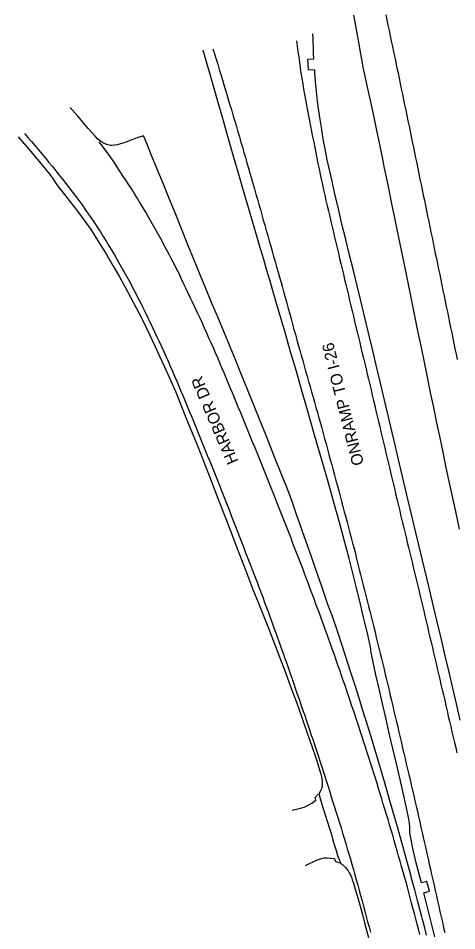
# Model space of a CAD drawing. Extents: x 1948091 to 1975253, y 787267 to 823306.
# Drawn here: x 1966396.6 to 1966599.2, y 789115.5 to 789536.5 of the extents above; entities that cross this region are included whole.
import ezdxf

# ---------------------------------------------------------------- set-up
doc = ezdxf.new("R2010")
doc.units = 0
for name, color, linetype in [('RD_EX_Pavement_Markings', 7, 'Continuous'), ('RD_EX_Road', 7, 'Continuous'), ('RD_TX_RoadID', 7, 'Continuous')]:
    doc.layers.add(name, color=color, linetype=linetype)

msp = doc.modelspace()

# ---------------------------------------------------------------- linework, layer by layer
at = {"layer": 'RD_EX_Pavement_Markings'}
for points in [[(1966566.37, 789538.15), (1966566.89, 789535.71), (1966567.41, 789533.26), (1966567.92, 789530.82), (1966568.44, 789528.37), (1966568.96, 789525.92), (1966569.47, 789523.48), (1966569.99, 789521.03), (1966570.51, 789518.59), (1966571.02, 789516.14), (1966571.54, 789513.7), (1966572.05, 789511.25), (1966572.57, 789508.81), (1966573.08, 789506.36), (1966573.58, 789503.91), (1966574.09, 789501.46), (1966574.6, 789499.01), (1966575.1, 789496.57), (1966575.61, 789494.12), (1966576.12, 789491.67), (1966576.62, 789489.22), (1966577.13, 789486.77), (1966577.63, 789484.33), (1966578.14, 789481.88), (1966578.65, 789479.43), (1966579.15, 789476.98), (1966579.66, 789474.54), (1966580.17, 789472.09), (1966580.67, 789469.64), (1966581.18, 789467.19), (1966581.68, 789464.74), (1966582.19, 789462.3), (1966582.7, 789459.85), (1966583.2, 789457.4), (1966583.71, 789454.95), (1966584.22, 789452.5), (1966584.72, 789450.06), (1966585.23, 789447.61), (1966585.74, 789445.16), (1966586.24, 789442.71), (1966586.75, 789440.27), (1966587.25, 789437.82), (1966587.76, 789435.37), (1966588.27, 789432.92), (1966588.77, 789430.47), (1966589.28, 789428.03), (1966589.78, 789425.58), (1966590.29, 789423.13), (1966590.79, 789420.68), (1966591.3, 789418.23), (1966591.8, 789415.78), (1966592.31, 789413.34), (1966592.81, 789410.89), (1966593.32, 789408.44), (1966593.82, 789405.99), (1966594.33, 789403.54), (1966594.83, 789401.1), (1966595.34, 789398.65), (1966595.84, 789396.2), (1966596.35, 789393.75), (1966596.85, 789391.3), (1966597.36, 789388.85), (1966597.86, 789386.41), (1966598.37, 789383.96), (1966598.88, 789381.51), (1966599.38, 789379.06)], [(1966525.18, 789526.08), (1966525.51, 789523.61), (1966525.85, 789521.13), (1966526.18, 789518.65), (1966526.51, 789516.18), (1966526.85, 789513.7), (1966527.22, 789511.23), (1966527.62, 789508.76), (1966528.02, 789506.3), (1966528.42, 789503.83), (1966528.82, 789501.37), (1966529.25, 789498.9), (1966529.73, 789496.45), (1966530.21, 789494), (1966530.69, 789491.55), (1966531.16, 789489.1), (1966531.64, 789486.65), (1966532.12, 789484.2), (1966532.61, 789481.75), (1966533.1, 789479.3), (1966533.58, 789476.85), (1966534.07, 789474.4), (1966534.56, 789471.95), (1966535.05, 789469.51), (1966535.58, 789467.07), (1966536.11, 789464.63), (1966536.63, 789462.19), (1966537.16, 789459.75), (1966537.68, 789457.31), (1966538.22, 789454.87), (1966538.79, 789452.44), (1966539.36, 789450.01), (1966539.93, 789447.58), (1966540.5, 789445.15), (1966541.07, 789442.72), (1966541.64, 789440.3), (1966542.21, 789437.87), (1966542.79, 789435.44), (1966543.36, 789433.01), (1966543.94, 789430.58), (1966544.51, 789428.16), (1966545.09, 789425.73), (1966545.66, 789423.3), (1966546.24, 789420.88), (1966546.81, 789418.45), (1966547.39, 789416.02), (1966547.96, 789413.59), (1966548.54, 789411.17), (1966549.12, 789408.74), (1966549.7, 789406.31), (1966550.27, 789403.89), (1966550.85, 789401.46), (1966551.43, 789399.03), (1966552.01, 789396.61), (1966552.59, 789394.18), (1966553.17, 789391.75), (1966553.76, 789389.33), (1966554.35, 789386.9), (1966554.93, 789384.48), (1966555.52, 789382.05), (1966556.11, 789379.63), (1966556.69, 789377.2), (1966557.28, 789374.78), (1966557.87, 789372.35), (1966558.45, 789369.93), (1966559.02, 789367.5), (1966559.59, 789365.07), (1966560.16, 789362.64), (1966560.73, 789360.21), (1966561.31, 789357.78), (1966561.88, 789355.35), (1966562.45, 789352.93), (1966563.02, 789350.5), (1966563.59, 789348.07), (1966564.16, 789345.64), (1966564.75, 789343.21), (1966565.33, 789340.79), (1966565.91, 789338.36), (1966566.49, 789335.94), (1966567.07, 789333.51), (1966567.65, 789331.09), (1966568.23, 789328.66), (1966568.81, 789326.24), (1966569.39, 789323.81), (1966569.97, 789321.38), (1966570.55, 789318.96), (1966571.12, 789316.53), (1966571.7, 789314.1), (1966572.28, 789311.68), (1966572.85, 789309.25), (1966573.43, 789306.82), (1966574, 789304.39), (1966574.58, 789301.97), (1966575.16, 789299.54), (1966575.74, 789297.11), (1966576.33, 789294.69), (1966576.91, 789292.26), (1966577.5, 789289.84), (1966578.09, 789287.41), (1966578.67, 789284.99), (1966579.26, 789282.56), (1966579.85, 789280.14), (1966580.43, 789277.71), (1966581.02, 789275.29), (1966581.61, 789272.86), (1966582.18, 789270.43), (1966582.76, 789268.01), (1966583.33, 789265.58), (1966583.9, 789263.15), (1966584.48, 789260.72), (1966585.05, 789258.29), (1966585.62, 789255.86), (1966586.2, 789253.43), (1966586.77, 789251.01), (1966587.34, 789248.58), (1966587.92, 789246.15), (1966588.49, 789243.72), (1966589.07, 789241.29), (1966589.64, 789238.86), (1966590.2, 789236.43), (1966590.77, 789234), (1966591.34, 789231.57), (1966591.9, 789229.14), (1966592.47, 789226.71), (1966593.03, 789224.28), (1966593.6, 789221.85), (1966594.16, 789219.42), (1966594.72, 789216.99), (1966595.28, 789214.56), (1966595.85, 789212.13), (1966596.41, 789209.7), (1966596.98, 789207.27), (1966597.55, 789204.84), (1966598.13, 789202.41), (1966598.7, 789199.98), (1966599.27, 789197.55)], [(1966486.58, 789522.44), (1966487.31, 789520.05), (1966488.05, 789517.66), (1966488.78, 789515.28), (1966489.5, 789512.88), (1966490.23, 789510.49), (1966490.95, 789508.1), (1966491.67, 789505.71), (1966492.39, 789503.32), (1966493.11, 789500.92), (1966493.83, 789498.53), (1966494.55, 789496.14), (1966495.27, 789493.75), (1966495.99, 789491.36), (1966496.71, 789488.96), (1966497.42, 789486.57), (1966498.11, 789484.17), (1966498.81, 789481.77), (1966499.51, 789479.37), (1966500.2, 789476.98), (1966500.9, 789474.58), (1966501.59, 789472.18), (1966502.29, 789469.78), (1966502.98, 789467.39), (1966503.68, 789464.99), (1966504.37, 789462.59), (1966505.05, 789460.19), (1966505.73, 789457.79), (1966506.42, 789455.39), (1966507.1, 789452.99), (1966507.79, 789450.59), (1966508.47, 789448.19), (1966509.15, 789445.8), (1966509.84, 789443.4), (1966510.52, 789441), (1966511.21, 789438.6), (1966511.89, 789436.2), (1966512.57, 789433.8), (1966513.25, 789431.4), (1966513.93, 789429), (1966514.61, 789426.6), (1966515.29, 789424.2), (1966515.97, 789421.8), (1966516.65, 789419.41), (1966517.33, 789417.01), (1966518.01, 789414.61), (1966518.69, 789412.21), (1966519.37, 789409.8), (1966520.03, 789407.4), (1966520.69, 789404.99), (1966521.36, 789402.59), (1966522.02, 789400.18), (1966522.68, 789397.78), (1966523.35, 789395.37), (1966524.01, 789392.97), (1966524.67, 789390.56), (1966525.34, 789388.16), (1966526, 789385.75), (1966526.66, 789383.35), (1966527.34, 789380.94), (1966528.02, 789378.55), (1966528.71, 789376.15), (1966529.39, 789373.74), (1966530.07, 789371.34), (1966530.76, 789368.94), (1966531.44, 789366.54), (1966532.12, 789364.14), (1966532.81, 789361.74), (1966533.49, 789359.34), (1966534.17, 789356.94), (1966534.85, 789354.54), (1966535.52, 789352.14), (1966536.18, 789349.73), (1966536.84, 789347.33), (1966537.49, 789344.92), (1966538.15, 789342.51), (1966538.81, 789340.1), (1966539.46, 789337.7), (1966540.12, 789335.29), (1966540.78, 789332.88), (1966541.43, 789330.47), (1966542.09, 789328.07), (1966542.75, 789325.66), (1966543.4, 789323.25), (1966544.05, 789320.84), (1966544.69, 789318.43), (1966545.33, 789316.02), (1966545.97, 789313.61), (1966546.61, 789311.2), (1966547.25, 789308.79), (1966547.9, 789306.38), (1966548.54, 789303.97), (1966549.18, 789301.56), (1966549.82, 789299.14), (1966550.46, 789296.73), (1966551.1, 789294.32), (1966551.73, 789291.91), (1966552.34, 789289.49), (1966552.95, 789287.07), (1966553.56, 789284.65), (1966554.17, 789282.23), (1966554.78, 789279.81), (1966555.39, 789277.39), (1966556, 789274.98), (1966556.61, 789272.56), (1966557.22, 789270.14), (1966557.83, 789267.72), (1966558.44, 789265.3), (1966559.05, 789262.88), (1966559.65, 789260.46), (1966560.24, 789258.03), (1966560.84, 789255.61), (1966561.43, 789253.19), (1966562.03, 789250.76), (1966562.62, 789248.34), (1966563.21, 789245.92), (1966563.81, 789243.49), (1966564.4, 789241.07), (1966565, 789238.64), (1966565.59, 789236.22), (1966566.19, 789233.8), (1966566.76, 789231.37), (1966567.33, 789228.94), (1966567.91, 789226.51), (1966568.48, 789224.08), (1966569.05, 789221.66), (1966569.62, 789219.23), (1966570.19, 789216.8), (1966570.77, 789214.37), (1966571.34, 789211.94), (1966571.91, 789209.51), (1966572.48, 789207.08), (1966573.06, 789204.65), (1966573.62, 789202.22), (1966574.19, 789199.79), (1966574.76, 789197.36), (1966575.33, 789194.93), (1966575.89, 789192.5), (1966576.46, 789190.07), (1966577.03, 789187.64), (1966577.59, 789185.21), (1966578.16, 789182.78), (1966578.73, 789180.35), (1966579.29, 789177.91), (1966579.86, 789175.48), (1966580.43, 789173.05), (1966580.98, 789170.62), (1966581.53, 789168.19), (1966582.08, 789165.75), (1966582.63, 789163.32), (1966583.18, 789160.88), (1966583.74, 789158.45), (1966584.29, 789156.01), (1966584.84, 789153.58), (1966585.39, 789151.14), (1966585.94, 789148.71), (1966586.49, 789146.28), (1966587.04, 789143.84), (1966587.59, 789141.41), (1966588.14, 789138.97), (1966588.69, 789136.54), (1966589.24, 789134.1), (1966589.79, 789131.67), (1966590.34, 789129.23), (1966590.89, 789126.8), (1966591.44, 789124.36), (1966591.99, 789121.92), (1966592.54, 789119.49), (1966593.09, 789117.05), (1966593.64, 789114.62)], [(1966399.5, 789483.33), (1966401.15, 789481.46), (1966402.81, 789479.59), (1966404.44, 789477.7), (1966406.04, 789475.78), (1966407.64, 789473.86), (1966409.24, 789471.94), (1966410.83, 789470.02), (1966412.4, 789468.07), (1966413.96, 789466.13), (1966415.53, 789464.18), (1966417.1, 789462.23), (1966418.67, 789460.29), (1966420.2, 789458.32), (1966421.7, 789456.32), (1966423.21, 789454.33), (1966424.71, 789452.33), (1966426.21, 789450.34), (1966427.62, 789448.27), (1966429.02, 789446.21), (1966430.43, 789444.14), (1966431.83, 789442.08), (1966433.24, 789440.01), (1966434.58, 789437.91), (1966435.89, 789435.78), (1966437.2, 789433.66), (1966438.51, 789431.53), (1966439.82, 789429.4), (1966441.13, 789427.28), (1966442.37, 789425.11), (1966443.6, 789422.93), (1966444.83, 789420.76), (1966446.06, 789418.58), (1966447.29, 789416.41), (1966448.47, 789414.21), (1966449.62, 789411.99), (1966450.77, 789409.78), (1966451.92, 789407.56), (1966453.07, 789405.34), (1966454.19, 789403.11), (1966455.28, 789400.86), (1966456.37, 789398.61), (1966457.45, 789396.36), (1966458.54, 789394.11), (1966459.62, 789391.86), (1966460.67, 789389.59), (1966461.72, 789387.33), (1966462.78, 789385.06), (1966463.83, 789382.79), (1966464.86, 789380.52), (1966465.87, 789378.23), (1966466.87, 789375.94), (1966467.87, 789373.66), (1966468.88, 789371.37), (1966469.86, 789369.07), (1966470.83, 789366.77), (1966471.8, 789364.47), (1966472.76, 789362.16), (1966473.73, 789359.86), (1966474.7, 789357.56), (1966475.65, 789355.25), (1966476.6, 789352.94), (1966477.54, 789350.63), (1966478.49, 789348.32), (1966479.44, 789346.01), (1966480.38, 789343.69), (1966481.32, 789341.38), (1966482.25, 789339.06), (1966483.19, 789336.75), (1966484.12, 789334.43), (1966485.06, 789332.12), (1966485.99, 789329.8), (1966486.92, 789327.49), (1966487.85, 789325.17), (1966488.78, 789322.86), (1966489.71, 789320.54), (1966490.64, 789318.22), (1966491.57, 789315.91), (1966492.49, 789313.59), (1966493.4, 789311.26), (1966494.3, 789308.93), (1966495.21, 789306.61), (1966496.12, 789304.28), (1966497.02, 789301.95), (1966497.93, 789299.63), (1966498.83, 789297.3), (1966499.73, 789294.97), (1966500.63, 789292.64), (1966501.53, 789290.32), (1966502.43, 789287.99), (1966503.33, 789285.66), (1966504.23, 789283.33), (1966505.13, 789281), (1966506.04, 789278.67), (1966506.94, 789276.34), (1966507.82, 789274.01), (1966508.69, 789271.67), (1966509.56, 789269.33), (1966510.43, 789266.99), (1966511.3, 789264.65), (1966512.17, 789262.31), (1966513.04, 789259.97), (1966513.91, 789257.63), (1966514.75, 789255.28), (1966515.59, 789252.93), (1966516.44, 789250.58), (1966517.28, 789248.23), (1966518.12, 789245.88), (1966518.97, 789243.53), (1966519.81, 789241.18), (1966520.65, 789238.83), (1966521.47, 789236.47), (1966522.29, 789234.11), (1966523.1, 789231.75), (1966523.92, 789229.39), (1966524.73, 789227.03), (1966525.55, 789224.67), (1966526.36, 789222.31), (1966527.18, 789219.94), (1966527.98, 789217.58), (1966528.79, 789215.22), (1966529.6, 789212.85), (1966530.4, 789210.49), (1966531.21, 789208.13), (1966532.01, 789205.76), (1966532.82, 789203.4), (1966533.61, 789201.03), (1966534.38, 789198.65), (1966535.15, 789196.28), (1966535.91, 789193.9), (1966536.68, 789191.52), (1966537.45, 789189.14), (1966538.22, 789186.76), (1966538.98, 789184.39), (1966539.75, 789182.01), (1966540.5, 789179.62), (1966541.25, 789177.24), (1966542, 789174.86), (1966542.75, 789172.47), (1966543.5, 789170.09), (1966544.25, 789167.7), (1966545, 789165.32), (1966545.75, 789162.94), (1966546.48, 789160.54), (1966547.19, 789158.15), (1966547.9, 789155.75), (1966548.61, 789153.36), (1966549.32, 789150.96), (1966550.03, 789148.57), (1966550.74, 789146.17), (1966551.45, 789143.77), (1966552.11, 789141.36), (1966552.78, 789138.95), (1966553.45, 789136.54), (1966554.12, 789134.14), (1966554.78, 789131.73), (1966555.45, 789129.32), (1966556.11, 789126.91), (1966556.75, 789124.49), (1966557.39, 789122.07), (1966558.03, 789119.66), (1966558.67, 789117.24), (1966559.32, 789114.83)], [(1966582.14, 789113.78), (1966581.51, 789116.19), (1966580.87, 789118.61), (1966580.23, 789121.03), (1966579.6, 789123.45), (1966578.96, 789125.86), (1966578.33, 789128.28), (1966577.69, 789130.7), (1966577.06, 789133.12), (1966576.42, 789135.53), (1966575.75, 789137.94), (1966575.06, 789140.34), (1966574.38, 789142.75), (1966573.7, 789145.15), (1966573.01, 789147.56), (1966572.33, 789149.96), (1966571.65, 789152.36), (1966570.96, 789154.77), (1966570.28, 789157.17), (1966569.59, 789159.57), (1966568.9, 789161.98), (1966568.18, 789164.37), (1966567.45, 789166.76), (1966566.73, 789169.15), (1966566, 789171.54), (1966565.27, 789173.93), (1966564.55, 789176.32), (1966563.82, 789178.71), (1966563.1, 789181.1), (1966562.37, 789183.5), (1966561.61, 789185.88), (1966560.85, 789188.26), (1966560.1, 789190.64), (1966559.34, 789193.02), (1966558.58, 789195.4), (1966557.82, 789197.78), (1966557.06, 789200.16), (1966556.3, 789202.54), (1966555.54, 789204.92), (1966554.79, 789207.3), (1966553.99, 789209.67), (1966553.19, 789212.04), (1966552.39, 789214.41), (1966551.59, 789216.77), (1966550.79, 789219.14), (1966549.99, 789221.5), (1966549.19, 789223.87), (1966548.39, 789226.24), (1966547.59, 789228.6), (1966546.79, 789230.97), (1966545.99, 789233.34), (1966545.16, 789235.69), (1966544.32, 789238.05), (1966543.49, 789240.4), (1966542.65, 789242.75), (1966541.82, 789245.11), (1966540.98, 789247.46), (1966540.15, 789249.81), (1966539.31, 789252.17), (1966538.48, 789254.52), (1966537.63, 789256.87), (1966536.76, 789259.21), (1966535.89, 789261.55), (1966535.02, 789263.89), (1966534.15, 789266.23), (1966533.28, 789268.57), (1966532.41, 789270.91), (1966531.54, 789273.25), (1966530.67, 789275.59), (1966529.8, 789277.93), (1966528.92, 789280.27), (1966528.02, 789282.6), (1966527.12, 789284.93), (1966526.22, 789287.25), (1966525.33, 789289.58), (1966524.43, 789291.91), (1966523.53, 789294.24), (1966522.63, 789296.57), (1966521.73, 789298.9), (1966520.83, 789301.23), (1966519.93, 789303.56), (1966519.01, 789305.88), (1966518.09, 789308.2), (1966517.16, 789310.52), (1966516.24, 789312.84), (1966515.32, 789315.16), (1966514.39, 789317.48), (1966513.47, 789319.79), (1966512.55, 789322.11), (1966511.62, 789324.43), (1966510.7, 789326.75), (1966509.77, 789329.07), (1966508.83, 789331.38), (1966507.89, 789333.7), (1966506.95, 789336.01), (1966506.01, 789338.32), (1966505.07, 789340.63), (1966504.12, 789342.94), (1966503.18, 789345.25), (1966502.24, 789347.57), (1966501.3, 789349.88), (1966500.35, 789352.19), (1966499.41, 789354.5), (1966498.45, 789356.81), (1966497.48, 789359.11), (1966496.52, 789361.41), (1966495.55, 789363.72), (1966494.59, 789366.02), (1966493.62, 789368.32), (1966492.66, 789370.63), (1966491.69, 789372.93), (1966490.73, 789375.24), (1966489.77, 789377.54), (1966488.78, 789379.83), (1966487.77, 789382.12), (1966486.77, 789384.4), (1966485.76, 789386.68), (1966484.75, 789388.97), (1966483.74, 789391.25), (1966482.73, 789393.54), (1966481.72, 789395.82), (1966480.69, 789398.1), (1966479.62, 789400.35), (1966478.55, 789402.61), (1966477.48, 789404.86), (1966476.4, 789407.12), (1966475.33, 789409.37), (1966474.26, 789411.63), (1966473.19, 789413.88), (1966472.12, 789416.14), (1966471.05, 789418.4), (1966469.92, 789420.62), (1966468.76, 789422.83), (1966467.6, 789425.05), (1966466.44, 789427.26), (1966465.28, 789429.47), (1966464.12, 789431.68), (1966462.97, 789433.9), (1966461.75, 789436.08), (1966460.53, 789438.25), (1966459.31, 789440.43), (1966458.09, 789442.61), (1966456.87, 789444.79), (1966455.65, 789446.97), (1966454.34, 789449.09), (1966453.02, 789451.21), (1966451.7, 789453.33), (1966450.38, 789455.45), (1966449.06, 789457.57), (1966447.72, 789459.69), (1966446.36, 789461.78), (1966444.99, 789463.87), (1966443.62, 789465.96), (1966442.25, 789468.05), (1966440.89, 789470.14), (1966439.44, 789472.18), (1966437.96, 789474.19), (1966436.48, 789476.2), (1966435, 789478.21), (1966434.08, 789479.46)]]:
    msp.add_lwpolyline(points, dxfattribs=at)
at = {"layer": 'RD_EX_Road'}
for points in [[(1966551.45, 789537.85), (1966552.5, 789532.29), (1966553.62, 789526.16), (1966554.7, 789520.07), (1966555.45, 789515.93), (1966555.86, 789513.79), (1966556.26, 789511.92), (1966556.78, 789509.58), (1966557.98, 789504.07), (1966559.89, 789495.23), (1966560.97, 789490.16), (1966562.12, 789484.73), (1966563.33, 789478.96), (1966564.55, 789473.09), (1966565.73, 789467.38), (1966567.29, 789459.69), (1966569.06, 789450.95), (1966570.25, 789445.13), (1966571.52, 789438.97), (1966572.87, 789432.47), (1966574.26, 789425.77), (1966575.66, 789419.02), (1966577.06, 789412.2), (1966578.47, 789405.33), (1966579.88, 789398.43), (1966581.28, 789391.53), (1966582.69, 789384.65), (1966584.09, 789377.76), (1966585.5, 789370.85), (1966586.93, 789363.89), (1966588.37, 789356.86), (1966589.84, 789349.79), (1966591.29, 789342.85), (1966592.68, 789336.27), (1966594.01, 789330.03), (1966595.28, 789324.13), (1966596.48, 789318.63), (1966598.54, 789308.99), (1966600.25, 789300.76)], [(1966600.82, 789212.58), (1966599.06, 789220.13), (1966597.35, 789227.43), (1966595.62, 789234.82), (1966593.86, 789242.3), (1966592.08, 789249.88), (1966590.27, 789257.48), (1966588.45, 789265.07), (1966586.52, 789273.08), (1966584.38, 789281.98), (1966582.23, 789290.95), (1966580.27, 789299.18), (1966578.43, 789306.95), (1966576.64, 789314.57), (1966574.79, 789322.43), (1966572.8, 789330.91), (1966570.92, 789338.92), (1966569.42, 789345.34), (1966567.41, 789353.85), (1966565.88, 789360.26), (1966564, 789368.11), (1966561.99, 789376.48), (1966560.08, 789384.43), (1966558.26, 789391.97), (1966556.55, 789399.1), (1966554.87, 789406.05), (1966553.16, 789413.06), (1966551.42, 789420.13), (1966549.65, 789427.27), (1966547.89, 789434.4), (1966546.18, 789441.49), (1966544.51, 789448.52), (1966542.88, 789455.5), (1966541.42, 789461.88), (1966539.37, 789471.17), (1966538.35, 789476.3), (1966537.67, 789479.99), (1966537.16, 789482.89), (1966536.64, 789486.08), (1966536.07, 789489.72), (1966535.5, 789493.75), (1966534.93, 789498.13), (1966534.42, 789502.7), (1966533.97, 789507.28), (1966533.66, 789511.09), (1966533.57, 789512.65), (1966530.66, 789512.49), (1966530.41, 789517.67), (1966533.2, 789517.84), (1966533.08, 789520.61), (1966532.98, 789523.1), (1966532.88, 789525.32), (1966532.81, 789527.26), (1966532.74, 789528.96), (1966532.73, 789529.33)], [(1966589.05, 789112.76), (1966587.41, 789119.49), (1966585.74, 789126.24), (1966584.04, 789133.03), (1966586.53, 789133.7), (1966585.36, 789138.16), (1966582.91, 789137.53), (1966580.45, 789146.86), (1966578.75, 789154.15), (1966577.77, 789159.11), (1966577.55, 789160.54), (1966577.51, 789161.25), (1966577.58, 789162.16), (1966577.55, 789163.44), (1966577.39, 789165.07), (1966577.05, 789167.01), (1966576.41, 789170.06), (1966575.33, 789175), (1966573.79, 789181.85), (1966571.77, 789190.67), (1966569.72, 789199.57), (1966568.04, 789206.7), (1966566.54, 789213.05), (1966565.03, 789219.65), (1966563.48, 789226.49), (1966561.87, 789233.59), (1966560.57, 789239.4), (1966559.93, 789242.39), (1966559.68, 789243.73), (1966559.54, 789244.61), (1966559.44, 789245.36), (1966559.32, 789246.32), (1966558.9, 789248.47), (1966557.92, 789252.75), (1966556.49, 789258.78), (1966554.7, 789266.16), (1966552.84, 789273.77), (1966551.19, 789280.45), (1966549.45, 789287.25), (1966547.34, 789295.23), (1966545, 789303.85), (1966542.58, 789312.59), (1966540.07, 789321.49), (1966537.46, 789330.63), (1966534.76, 789340.03), (1966533.38, 789344.83), (1966531.98, 789349.71), (1966530.58, 789354.59), (1966527.81, 789364.18), (1966525.09, 789373.53), (1966522.45, 789382.61), (1966519.87, 789391.5), (1966517.19, 789400.69), (1966514.4, 789410.25), (1966512.96, 789415.15), (1966511.51, 789420.11), (1966510.03, 789425.15), (1966508.57, 789430.14), (1966505.78, 789439.64), (1966503.13, 789448.64), (1966500.39, 789457.98), (1966498.97, 789462.82), (1966496.23, 789472.23), (1966493.77, 789480.83), (1966491.41, 789489.13), (1966488.97, 789497.63), (1966486.79, 789505.18), (1966485.24, 789510.65), (1966484.1, 789514.68), (1966482.99, 789518.57), (1966482.07, 789521.77)], [(1966585.25, 789113.39), (1966584.37, 789116.83), (1966583.38, 789120.63), (1966583.04, 789121.96), (1966582.29, 789124.82), (1966581.08, 789129.39), (1966579.75, 789134.34), (1966578.32, 789139.68), (1966578.1, 789140.65), (1966576, 789148.39), (1966573.84, 789156.25), (1966571.83, 789163.4), (1966569.86, 789170.25), (1966567.85, 789177.19), (1966565.82, 789184.19), (1966562.68, 789194.72), (1966560.09, 789203.37), (1966558.19, 789209.41), (1966555.7, 789217.54), (1966554.07, 789222.77), (1966552.35, 789228.2), (1966550.58, 789233.74), (1966548.74, 789239.48), (1966546.56, 789246.19), (1966544.07, 789253.7), (1966541.75, 789260.41), (1966539.7, 789266.07), (1966536.69, 789274.77), (1966534.32, 789281.67), (1966531.81, 789288.95), (1966529.63, 789294.89), (1966526.74, 789303.22), (1966524.93, 789308.48), (1966523.01, 789313.95), (1966520.92, 789319.68), (1966518.16, 789326.42), (1966514.87, 789334.44), (1966511.4, 789343.22), (1966508.37, 789350.78), (1966505.83, 789357.28), (1966502.61, 789365.18), (1966499.46, 789372.78), (1966497.1, 789378.62), (1966494.51, 789384.93), (1966491.63, 789391.92), (1966489.03, 789398.23), (1966485.92, 789405.41), (1966483.22, 789411.86), (1966480.64, 789418.14), (1966477.88, 789424.83), (1966474.99, 789431.9), (1966472.03, 789439.34), (1966469.12, 789446.67), (1966466.4, 789453.38), (1966463.69, 789459.96), (1966460.84, 789466.93), (1966458.25, 789473.24), (1966456.34, 789477.88), (1966455.1, 789480.87), (1966454.52, 789482.28), (1966452.06, 789481.49), (1966448.58, 789480.29), (1966446.8, 789479.54), (1966445.34, 789478.96), (1966443.94, 789478.51), (1966442.51, 789478.15), (1966441.07, 789477.9), (1966439.78, 789477.82), (1966439.21, 789477.85), (1966438.66, 789477.92), (1966438.09, 789478.05), (1966437.52, 789478.24), (1966436.34, 789478.75), (1966435.24, 789479.35), (1966434.22, 789480.03), (1966433.2, 789480.91), (1966432.14, 789482.03), (1966430.75, 789483.62), (1966428.99, 789485.71), (1966426.85, 789488.23), (1966424.15, 789491.33), (1966420.61, 789495.36)], [(1966396.64, 789481.72), (1966402.34, 789475.1), (1966406.33, 789470.38), (1966409.24, 789466.88), (1966411.18, 789464.46), (1966412.47, 789462.74), (1966413.43, 789461.32), (1966414.21, 789460.12), (1966414.97, 789459.04), (1966416.11, 789457.55), (1966418.03, 789455.15), (1966420.67, 789451.8), (1966423.97, 789447.45), (1966427.33, 789442.91), (1966430.11, 789438.98), (1966432.55, 789435.34), (1966434.86, 789431.7), (1966437.35, 789427.56), (1966440.33, 789422.46), (1966443.36, 789417.16), (1966446.03, 789412.44), (1966448.54, 789407.85), (1966451.11, 789402.93), (1966453.52, 789398.21), (1966455.51, 789394.19), (1966457.43, 789390.22), (1966459.62, 789385.62), (1966461.94, 789380.67), (1966464.24, 789375.66), (1966466.27, 789371.16), (1966467.76, 789367.76), (1966469.36, 789363.94), (1966471.72, 789358.16), (1966474.41, 789351.53), (1966477, 789345.15), (1966479.53, 789338.89), (1966482.04, 789332.63), (1966484.53, 789326.32), (1966486.99, 789319.92), (1966489.48, 789313.4), (1966492.04, 789306.74), (1966494.64, 789299.97), (1966497.24, 789293.14), (1966499.84, 789286.31), (1966502.46, 789279.51), (1966505.05, 789272.89), (1966507.57, 789266.6), (1966510.06, 789260.46), (1966512.54, 789254.27), (1966515.02, 789247.95), (1966517.53, 789241.4), (1966520.06, 789234.66), (1966522.62, 789227.77), (1966525.12, 789220.91), (1966527.47, 789214.29), (1966529.78, 789207.62), (1966532.18, 789200.66), (1966534.19, 789194.75), (1966535.33, 789191.28), (1966535.94, 789189.26), (1966536.37, 789187.71), (1966536.67, 789186.47), (1966536.87, 789185.38), (1966536.99, 789184.34), (1966537.02, 789183.26), (1966536.95, 789182.24), (1966536.88, 789181.78), (1966536.66, 789180.98), (1966536.4, 789180.3), (1966536.1, 789179.74), (1966535.84, 789179.34), (1966535.64, 789179.06), (1966535.58, 789178.91), (1966535.56, 789178.75), (1966535.56, 789178.56), (1966535.8, 789177.57), (1966536.46, 789175.38), (1966537.4, 789172.39), (1966538.48, 789169.01), (1966539.54, 789165.63), (1966540.46, 789162.65), (1966541.26, 789159.93), (1966541.97, 789157.34), (1966542.67, 789154.86), (1966543.42, 789152.45), (1966544.17, 789150.24), (1966544.82, 789148.34), (1966545.12, 789147.56), (1966545.41, 789146.96), (1966545.69, 789146.53), (1966545.96, 789146.27), (1966546.52, 789145.87), (1966547.13, 789145.32), (1966547.76, 789144.66), (1966548.37, 789143.93), (1966548.96, 789143.12), (1966549.54, 789142.24), (1966550.06, 789141.28), (1966550.51, 789140.27), (1966550.95, 789139.06), (1966551.48, 789137.51), (1966552.33, 789134.67), (1966553.76, 789129.62), (1966555.42, 789123.63), (1966556.93, 789117.98), (1966558.4, 789112.32)], [(1966523.21, 789171.09), (1966526.44, 789171.86), (1966528.68, 789172.56), (1966530.56, 789173.45), (1966532.28, 789174.42), (1966534.12, 789175.67), (1966533.81, 789176.97), (1966535.15, 789178.45)], [(1966529.26, 789145.64), (1966534.33, 789148.1), (1966536.66, 789148.89), (1966537.95, 789149.19), (1966539.1, 789149.17), (1966540.94, 789149.03), (1966542.53, 789148.9), (1966543.33, 789147.46), (1966545.02, 789146.89)]]:
    msp.add_lwpolyline(points, dxfattribs=at)

# ---------------------------------------------------------------- texts
at = {"layer": 'RD_TX_RoadID'}
for s, rotation, p in [('ONRAMP TO I-26', 104.2223, (1966556.36, 789330.88)), ('HARBOR DR', 113.3584, (1966498.43, 789332.11))]:
    msp.add_text(s, height=5.4, rotation=rotation, dxfattribs=at).set_placement(p)

doc.saveas('drawing.dxf')
